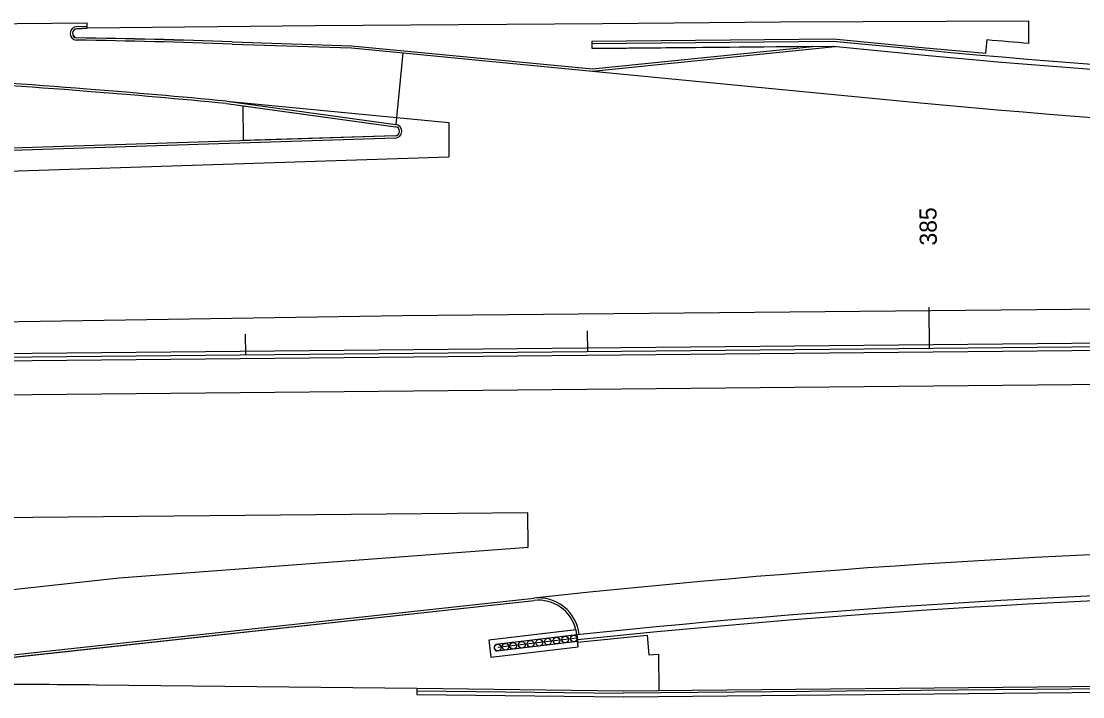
# Model space of a CAD drawing. Extents: x 2145147 to 2158018, y 137519 to 148068.
# Drawn here: x 2146242.4 to 2146552.9, y 142950.6 to 143148 of the extents above; entities that cross this region are included whole.
import ezdxf

# ---------------------------------------------------------------- set-up
doc = ezdxf.new("R2010")
doc.units = 0
for name, color, linetype in [('Default', 7, 'Continuous'), ('EX_Align_1', 7, 'Continuous'), ('EX_Align_1_Sta', 7, 'Continuous'), ('PR_Phasing_Pavement_6', 7, 'Continuous')]:
    doc.layers.add(name, color=color, linetype=linetype)

# ---------------------------------------------------------------- blocks, each defined once
blk = doc.blocks.new('Atenuator_TAU-II')
at = {"layer": 'Default'}
for p, q in [((0, 2.54), (-60.56, 2.54)), ((0, 2.54), (0, -2.54)), ((0, -2.54), (-60.56, -2.54))]:
    blk.add_line(p, q, dxfattribs=at)
for centre in [(-59.44, 0.01), (-53.62, 0.01), (-47.81, 0.01), (-41.34, 0.01), (-34.86, 0.01), (-28.38, 0.01), (-21.91, 0.01), (-15.43, 0.01), (-8.96, 0.01), (-2.48, 0.01)]:
    blk.add_circle(centre, 2.48, dxfattribs=at)
blk.add_arc((-59.13, 0), 2.91, 119.38082, 240.61918, dxfattribs=at)

msp = doc.modelspace()

# ---------------------------------------------------------------- linework, layer by layer
at = {"layer": 'EX_Align_1'}
msp.add_line((2145641.75, 143044.23), (2147351.75, 143060.44), dxfattribs=at)
for points in [[(2146507.88, 143064.44), (2146508, 143052.44)], [(2146307.95, 143056.54), (2146308, 143050.54)], [(2146407.94, 143057.49), (2146408, 143051.49)]]:
    msp.add_lwpolyline(points, dxfattribs=at)
at = {"layer": 'PR_Phasing_Pavement_6'}
for p, q in [((2146258.71, 143146.44), (2146261.73, 143146.53)), ((2146258.71, 143145.78), (2146261.73, 143145.93)), ((2146261.73, 143145.93), (2146261.72, 143147.51)), ((2146409.4, 143140.01), (2146409.38, 143141.51)), ((2146352.08, 143117.81), (2146354.09, 143138.72)), ((2146409.45, 143133.39), (2146505.38, 143124.16)), ((2146302.51, 143124.6), (2146367.43, 143118.35)), ((2146367.43, 143118.35), (2146367.52, 143108.35)), ((2145761.51, 143088.87), (2146367.52, 143108.35)), ((2146353.97, 143061.98), (2147732.51, 143075.05)), ((2145754.03, 143052.79), (2146353.97, 143061.98)), ((2145902.26, 143047.76), (2146643.98, 143054.79)), ((2145902.28, 143045.64), (2146644, 143052.67)), ((2146054.2, 143037.14), (2147732.72, 143053.05)), ((2146390.61, 143004.33), (2146054.29, 143001.14)), ((2146390.71, 142994.33), (2146390.61, 143004.33)), ((2146271.05, 142985.32), (2146390.71, 142994.33)), ((2146149.31, 142972.06), (2146271.05, 142985.32)), ((2146190.19, 142957.4), (2146392.33, 142979.42)), ((2146190.26, 142956.73), (2146392.4, 142978.75)), ((2146404.91, 142968.69), (2146405.08, 142967.2)), ((2146405.02, 142967.71), (2146381.78, 142964.94)), ((2146418.5, 142952.26), (2146358.08, 142952.96)), ((2146358.08, 142952.96), (2146358.1, 142951.29)), ((2146571.12, 142953.7), (2146418.5, 142952.26)), ((2146571.16, 142953.04), (2146418.51, 142951.59)), ((2146358.09, 142952.29), (2146418.51, 142951.59)), ((2146358.1, 142951.29), (2146418.5, 142950.59)), ((2146418.52, 142950.59), (2146571.22, 142952.04))]:
    msp.add_line(p, q, dxfattribs=at)
for points in [[(2146169.65, 143146.64), (2146261.72, 143147.51)], [(2146537.15, 143141.56), (2146537.09, 143147.98), (2146464.49, 143147.71), (2146412.4, 143147.27), (2146328.37, 143146.61), (2146261.73, 143145.93), (2146258.71, 143145.78)], [(2146304.14, 143141.99), (2146339.04, 143140.84), (2146409.45, 143134.06), (2146473.93, 143140.62), (2146409.4, 143140.01), (2146409.38, 143142.18), (2146479.94, 143142.85), (2146506.92, 143140.25)], [(2146409.38, 143141.51), (2146479.91, 143142.18), (2146506.86, 143139.59)], [(2146524.54, 143138.62), (2146524.89, 143142.61)], [(2146304.12, 143141.33), (2146339, 143140.18), (2146409.45, 143133.39)], [(2146304.14, 143141.99), (2146339.04, 143140.84), (2146409.45, 143134.06)], [(2146409.4, 143140.01), (2146479.85, 143140.68), (2146506.72, 143138.09)], [(2146409.45, 143133.39), (2146480.47, 143140.62)], [(2146409.45, 143134.06), (2146473.93, 143140.62)], [(2146302.43, 143123.94), (2146351.89, 143117.17)], [(2146302.51, 143124.6), (2146351.98, 143117.83)], [(2146307.41, 143113.09), (2146307.32, 143123.27), (2146351.89, 143117.17)], [(2146351.75, 143114.51), (2146066.74, 143105.35)], [(2146351.75, 143114.51), (2146307.41, 143113.09)], [(2146351.77, 143113.85), (2146066.76, 143104.68)], [(2146190.26, 142956.73), (2146392.4, 142978.75)], [(2146404.64, 142970.18), (2146379.15, 142967.15), (2146379.74, 142962.18), (2146405.32, 142965.22), (2146405.16, 142966.54), (2146405.13, 142966.53), (2146425.46, 142968.58), (2146425.99, 142962.79), (2146428.84, 142963.06)], [(2146428.84, 142963.06), (2146428.94, 142952.35), (2146418.5, 142952.26), (2146358.08, 142952.96), (2146264.57, 142954)]]:
    msp.add_lwpolyline(points, dxfattribs=at)
msp.add_lwpolyline([(2146404.73, 142970.19), (2146379.15, 142967.15), (2146379.74, 142962.18), (2146405.32, 142965.22)], close=True, dxfattribs=at)
for centre, radius, start, end in [((2146258.72, 143144.44), 2, 90.5326, 265.6294), ((2146258.72, 143144.44), 1.33, 90.5326, 264.8247), ((2146258.78, 143144.44), 1.34, 92.8888, 262.4686), ((2146229.27, 141022.73), 2119.92, 87.97661, 89.2081), ((2146215.04, 140443.81), 2699.65, 88.10864, 89.07547), ((2146229.27, 141022.73), 2120.59, 87.97663, 89.20748), ((2146725.04, 145405.44), 2271.66, 264.94532, 265.25581), ((2146725.04, 145405.44), 2276.33, 264.5, 270.54316), ((2146725.04, 145405.44), 2275.66, 264.5, 264.94532), ((2146725.04, 145405.44), 2277.83, 264.5, 270.54316), ((2146082.85, 140843.32), 2291.16, 85.52645, 88.09149), ((2146082.85, 140843.32), 2291.83, 85.52645, 88.09149), ((2146082.85, 140843.32), 2291.16, 84.50033, 85.52645), ((2146082.85, 140843.32), 2291.83, 84.5, 85.52645), ((2146725.04, 145405.44), 2291.83, 264.5, 270.54316), ((2146351.71, 143115.85), 2, 271.8413, 82.2008), ((2146351.71, 143115.85), 1.33, 271.8413, 82.2008), ((2146351.71, 143115.85), 1.33, 271.8413, 82.2008), ((2146678.1, 140355.96), 2638.97, 90.54316, 96.2165), ((2146678.1, 140355.96), 2626.97, 90.54316, 95.96903), ((2146678.1, 140355.96), 2625.47, 90.54316, 95.96889), ((2146393.63, 142967.49), 12, 6.0856, 96.2165), ((2146393.63, 142967.49), 11.33, 13.7467, 96.2165), ((2146393.63, 142967.49), 11.33, 13.7467, 96.2165), ((2146223.92, 139311.9), 3642.33, 89.36047, 90.5268)]:
    msp.add_arc(centre, radius, start, end, dxfattribs=at)

# ---------------------------------------------------------------- block references
at = {"layer": 'PR_Phasing_Pavement_6', "xscale": 0.39370000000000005, "yscale": 0.3937, "rotation": 6.797534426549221}
msp.add_blockref('Atenuator_TAU-II', (2146405.02, 142967.71), dxfattribs=at)

# ---------------------------------------------------------------- texts
at = {"layer": 'EX_Align_1_Sta'}
msp.add_text('385', height=5, rotation=90.5432, dxfattribs=at).set_placement((2146510.21, 143082.46))

doc.saveas('drawing.dxf')
